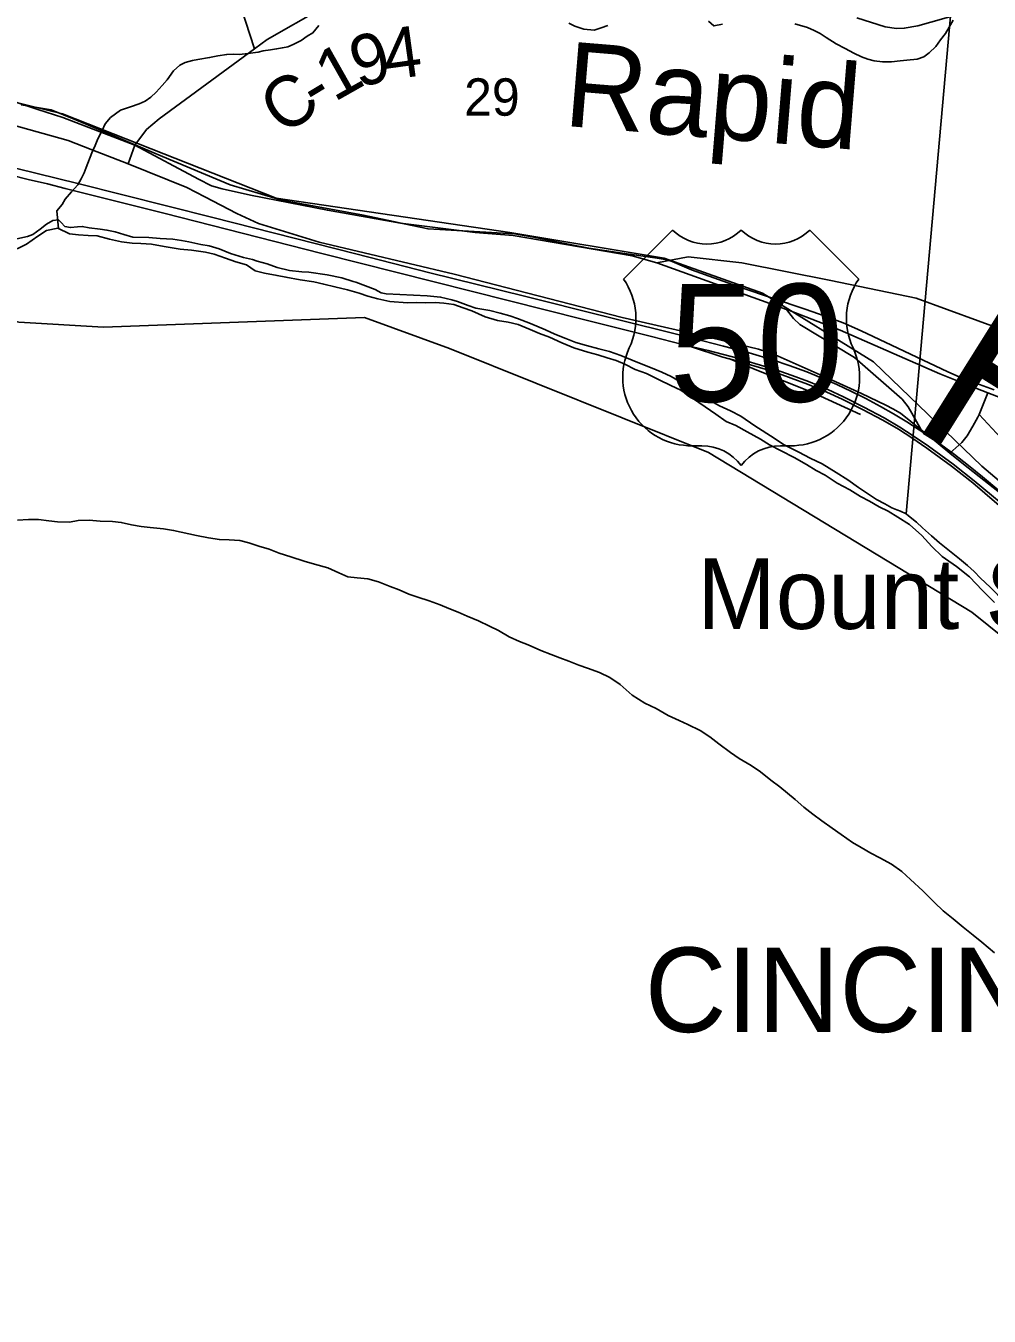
# Model space of a CAD drawing. Extents: x 0 to 34, y 0 to 22.
# Drawn here: x 4.65 to 5.729, y 14.739 to 16.185 of the extents above; entities that cross this region are included whole.
import ezdxf

# ---------------------------------------------------------------- set-up
doc = ezdxf.new("R2010")
doc.units = 0
for name, color, linetype in [('GM_X_City_Street', 7, 'Continuous'), ('GM_X_Corporation', 7, 'Continuous'), ('GM_X_Corporation_Text', 7, 'Continuous'), ('GM_X_County_Road', 7, 'Continuous'), ('GM_X_County_Road_Text', 7, 'Continuous'), ('GM_X_County_Text', 7, 'Continuous'), ('GM_X_Major_River', 7, 'Continuous'), ('GM_X_Minor_River', 7, 'Continuous'), ('GM_X_Minor_River_Text', 7, 'Continuous'), ('GM_X_Rail_Line', 7, 'Continuous'), ('GM_X_Section_Text', 7, 'Continuous'), ('GM_X_Unincorporated_Text', 7, 'Continuous'), ('GM_X_US_Location', 7, 'Continuous'), ('GM_X_US_Route', 7, 'Continuous'), ('GM_X_US_Shield', 7, 'Continuous')]:
    doc.layers.add(name, color=color, linetype=linetype)

msp = doc.modelspace()

# ---------------------------------------------------------------- linework, layer by layer
at = {"layer": 'GM_X_City_Street'}
for points in [[(5.6526, 15.7325), (5.6421, 15.751), (5.6381, 15.7581), (5.6313, 15.7667), (5.5781, 15.8133), (5.5166, 15.8504), (5.5098, 15.8571), (5.5019, 15.8673)], [(5.6849, 15.7062), (5.6984, 15.7183), (5.7041, 15.7255), (5.7107, 15.7365), (5.7163, 15.7467), (5.7175, 15.7496), (5.7275, 15.774)], [(5.7175, 15.7496), (5.7421, 15.7235), (5.752, 15.7145), (5.7596, 15.7096), (5.784, 15.6944)]]:
    msp.add_lwpolyline(points, dxfattribs=at)
at = {"layer": 'GM_X_Corporation'}
for points in [[(3.3535, 16.9293), (3.4766, 16.7367), (3.5579, 16.6419), (3.619, 16.5459), (3.7774, 16.2543), (3.8686, 16.1561), (3.9643, 16.0792), (4.2564, 15.9374), (4.3533, 15.9108), (4.4487, 15.8964), (4.6416, 15.8532), (4.7366, 15.8475), (5.0291, 15.8581), (5.1241, 15.8236), (5.4143, 15.7071), (5.7095, 15.5281), (5.8045, 15.4515), (6.1414, 15.0678), (6.2843, 14.8736), (6.3804, 14.7819), (6.459, 14.6859)], [(3.3535, 16.9293), (3.4766, 16.7367), (3.5579, 16.6419), (3.619, 16.5459), (3.7774, 16.2543), (3.8686, 16.1561), (3.9643, 16.0792), (4.2564, 15.9374), (4.3533, 15.9108), (4.4487, 15.8964), (4.6416, 15.8532), (4.7366, 15.8475), (5.0291, 15.8581), (5.1241, 15.8236), (5.4143, 15.7071), (5.7095, 15.5281), (5.8045, 15.4515), (6.1354, 15.0636), (6.1959, 14.9814), (6.2842, 14.8736), (6.3804, 14.7819), (6.459, 14.6859)], [(3.3535, 16.9293), (3.4766, 16.7367), (3.5579, 16.6419), (3.619, 16.5459), (3.7774, 16.2543), (3.8686, 16.1561), (3.9643, 16.0792), (4.2564, 15.9374), (4.3533, 15.9108), (4.4487, 15.8964), (4.6416, 15.8532), (4.7366, 15.8475), (5.0291, 15.8581), (5.1241, 15.8236), (5.4143, 15.7071), (5.7095, 15.5281), (5.8045, 15.4515), (6.1414, 15.0678), (6.2843, 14.8736), (6.3804, 14.7819), (6.459, 14.6859)], [(5.7092, 16.4608), (5.6358, 15.6382), (5.6294, 15.6414), (5.6253, 15.6426), (5.6197, 15.645), (5.6118, 15.6494), (5.6025, 15.6545), (5.5991, 15.6565), (5.5823, 15.6679), (5.5704, 15.6762), (5.5573, 15.6844), (5.5417, 15.6943), (5.5282, 15.7007), (5.5155, 15.7074), (5.4983, 15.7158), (5.4878, 15.7229), (5.4662, 15.737), (5.4505, 15.7476), (5.4389, 15.7536), (5.4266, 15.7592), (5.4049, 15.7711), (5.3814, 15.7868), (5.3724, 15.7923), (5.3623, 15.7971), (5.3496, 15.8024), (5.3353, 15.808), (5.3162, 15.8157), (5.3034, 15.8202), (5.2914, 15.8231), (5.2778, 15.8268), (5.2658, 15.8302), (5.2545, 15.8346), (5.2421, 15.8394), (5.2317, 15.8446), (5.2151, 15.8515), (5.2005, 15.8571), (5.1919, 15.86), (5.181, 15.8633), (5.1693, 15.8662), (5.1538, 15.8689), (5.1452, 15.8717), (5.1332, 15.8762), (5.1268, 15.8782), (5.1143, 15.8812), (5.0992, 15.8827), (5.0534, 15.8846), (5.0478, 15.8858), (5.0411, 15.8898), (5.0302, 15.8938), (5.0193, 15.8979), (5.0163, 15.8987), (5.0035, 15.9028), (4.9873, 15.9059), (4.9665, 15.909), (4.9589, 15.9096), (4.945, 15.9111), (4.931, 15.9144), (4.9201, 15.9185), (4.9089, 15.9214), (4.9036, 15.9231), (4.8934, 15.9256), (4.8788, 15.9301), (4.866, 15.9353), (4.8551, 15.9386), (4.8457, 15.94), (4.8321, 15.943), (4.8238, 15.9447), (4.8144, 15.9461), (4.8, 15.9468), (4.7875, 15.9478), (4.7693, 15.9483), (4.7592, 15.9512), (4.7498, 15.9541), (4.7404, 15.9562), (4.7328, 15.9571), (4.7207, 15.9589), (4.7128, 15.9603), (4.7075, 15.96), (4.6995, 15.9591), (4.6931, 15.9604), (4.689, 15.9646), (4.6861, 15.9677), (4.68, 15.9671), (4.6727, 15.9628), (4.6657, 15.9572), (4.6573, 15.9514), (4.6515, 15.9489), (4.6363, 15.9455)], [(5.7345, 15.7771), (5.7058, 15.7877), (5.6952, 15.7917), (5.6826, 15.7974), (5.5917, 15.8403), (5.5814, 15.8451), (5.5652, 15.8521), (5.5512, 15.8576), (5.5378, 15.8624), (5.5228, 15.8677), (5.4506, 15.892), (5.3953, 15.9117), (5.3876, 15.9151), (5.3736, 15.9209), (5.3682, 15.9227), (5.3638, 15.9238), (5.3569, 15.9248), (5.313, 15.9312), (5.2803, 15.9359), (5.2746, 15.9369), (5.2633, 15.9392), (5.2183, 15.9483), (5.1971, 15.9521), (5.1003, 15.9575), (5.0736, 15.9632), (5.0616, 15.9658), (5.028, 15.9729), (4.9363, 15.9896), (4.9313, 15.9911), (4.8785, 16.0068), (4.8026, 16.0386), (4.7287, 16.07), (4.7037, 16.0805), (4.6781, 16.0908), (4.6442, 16.0967)]]:
    msp.add_lwpolyline(points, dxfattribs=at)
msp.add_lwpolyline([(6.6267, 16.412), (6.5194, 15.3963), (5.7481, 15.5362), (5.7385, 15.5474), (5.73, 15.556), (5.7193, 15.5661), (5.7119, 15.5735), (5.7045, 15.5805), (5.6956, 15.5879), (5.6844, 15.5969), (5.6733, 15.6058), (5.6644, 15.6136), (5.6543, 15.6226), (5.6473, 15.6288), (5.6384, 15.6362), (5.6358, 15.6382), (5.7092, 16.4608)], close=True, dxfattribs=at)
at = {"layer": 'GM_X_County_Road'}
msp.add_line((4.7643, 16.0305), (4.7718, 16.0513), dxfattribs=at)
for points in [[(4.9057, 16.1593), (4.8909, 16.2054), (4.8786, 16.2563), (4.8733, 16.3037), (4.8803, 16.3426)], [(4.9057, 16.1593), (4.9201, 16.1698), (4.9815, 16.2049)], [(5.5805, 16.1941), (5.6125, 16.184), (5.625, 16.1822), (5.6337, 16.1824), (5.649, 16.1851), (5.6952, 16.1981)], [(4.7718, 16.0513), (4.7847, 16.0689), (4.799, 16.0807), (4.9057, 16.1593)], [(4.5521, 16.1152), (4.5559, 16.1144), (4.6024, 16.1062), (4.6382, 16.0994), (4.6632, 16.0913), (4.691, 16.0823), (4.7718, 16.0513)], [(4.7718, 16.0513), (4.8431, 16.0134), (4.8577, 16.0058), (4.8694, 16.0025), (4.9011, 15.9954), (4.9875, 15.9784), (5.0695, 15.9641), (5.1531, 15.9535), (5.1955, 15.9503), (5.3289, 15.9273), (5.3564, 15.9195), (5.5019, 15.8673), (5.5051, 15.8662), (5.5618, 15.8441), (5.6734, 15.795), (5.7072, 15.7818), (5.7275, 15.774), (5.7731, 15.7564)], [(5.3564, 15.9195), (5.3917, 15.9264), (5.4516, 15.9197), (5.5515, 15.8997), (5.647, 15.8798), (5.7513, 15.842), (5.8512, 15.7909), (5.9622, 15.7554), (6.0398, 15.7354), (6.1397, 15.7199), (6.2016, 15.7149)]]:
    msp.add_lwpolyline(points, dxfattribs=at)
at = {"layer": 'GM_X_Major_River'}
for points in [[(4.7686, 15.9416), (4.7568, 15.9429), (4.7432, 15.9461), (4.7296, 15.9498), (4.7194, 15.9503), (4.7084, 15.9509), (4.6986, 15.9522), (4.6854, 15.9584), (4.6728, 15.9556), (4.6632, 15.9493), (4.6502, 15.9404), (4.6399, 15.9352)], [(5.7349, 15.539), (5.7214, 15.5525), (5.7069, 15.5675), (5.6923, 15.5792), (5.6761, 15.5904), (5.6645, 15.6016), (5.6533, 15.6139), (5.6395, 15.6263), (5.6264, 15.6345), (5.6158, 15.6411), (5.6057, 15.6462), (5.5948, 15.6525), (5.5846, 15.6576), (5.5726, 15.665), (5.5587, 15.6728), (5.5452, 15.6817), (5.535, 15.6868), (5.5241, 15.6934), (5.5102, 15.7012), (5.4959, 15.7087), (5.4827, 15.7154), (5.4726, 15.722), (5.4579, 15.7302), (5.4451, 15.7372), (5.4342, 15.7419), (5.4226, 15.7501), (5.4106, 15.7583), (5.3835, 15.7769), (5.3722, 15.782), (5.3591, 15.7883), (5.3448, 15.7954), (5.3323, 15.8001), (5.3207, 15.806), (5.3109, 15.8099), (5.301, 15.8131), (5.2905, 15.8163), (5.2791, 15.8196), (5.2637, 15.8244), (5.2501, 15.8299), (5.2362, 15.8362), (5.2252, 15.8402), (5.2147, 15.8449), (5.2011, 15.8504), (5.1898, 15.8532), (5.178, 15.855), (5.1641, 15.859), (5.1494, 15.8657), (5.1396, 15.8692), (5.129, 15.8728), (5.118, 15.8745), (5.1082, 15.875), (5.0975, 15.8748), (5.0877, 15.875), (5.0771, 15.8748), (5.0574, 15.8762), (5.0438, 15.8791), (5.0328, 15.8823), (5.023, 15.8855), (5.0101, 15.8891), (4.9958, 15.8928), (4.9833, 15.8956), (4.9724, 15.8981), (4.9568, 15.9006), (4.941, 15.9035), (4.9311, 15.9052), (4.9171, 15.9081), (4.9065, 15.9105), (4.8968, 15.9171), (4.8847, 15.9207), (4.8734, 15.9247), (4.8606, 15.9291), (4.8507, 15.9315), (4.8352, 15.9337), (4.8223, 15.935), (4.8046, 15.9379), (4.7902, 15.9405), (4.7784, 15.941), (4.7686, 15.9416)], [(4.6404, 15.6312), (4.6526, 15.6318), (4.6636, 15.632), (4.6753, 15.6306), (4.6852, 15.6293), (4.6984, 15.6291), (4.7083, 15.6309), (4.7205, 15.6311), (4.733, 15.6301), (4.7466, 15.6295), (4.7565, 15.6286), (4.7678, 15.6261), (4.7788, 15.6241), (4.789, 15.6228), (4.8038, 15.6214), (4.8151, 15.6197), (4.8408, 15.614), (4.8541, 15.6115), (4.8665, 15.6094), (4.8775, 15.6092), (4.8893, 15.6083), (4.8995, 15.6058), (4.9108, 15.6022), (4.9221, 15.5986), (4.9334, 15.5943), (4.9463, 15.5899), (4.9614, 15.5851), (4.9731, 15.5819), (4.9878, 15.5778), (5.0002, 15.5723), (5.0104, 15.5676), (5.0206, 15.5667), (5.0328, 15.5654), (5.0448, 15.5621), (5.0577, 15.557), (5.0678, 15.553), (5.0788, 15.5483), (5.0886, 15.5447), (5.1014, 15.5407), (5.1139, 15.5364), (5.1236, 15.532), (5.1338, 15.5281), (5.144, 15.5237), (5.1568, 15.5182), (5.1692, 15.5123), (5.179, 15.5076), (5.1911, 15.5006), (5.2027, 15.4951), (5.2125, 15.4915), (5.2265, 15.4852), (5.2382, 15.4805), (5.248, 15.4769), (5.2578, 15.473), (5.2691, 15.4686), (5.2789, 15.4654), (5.2921, 15.4606), (5.3038, 15.4548), (5.3154, 15.447), (5.3289, 15.435), (5.3431, 15.426), (5.3556, 15.4202), (5.3691, 15.4123), (5.3815, 15.4068), (5.3913, 15.4021), (5.4049, 15.3955), (5.4158, 15.3885), (5.4259, 15.3807), (5.439, 15.371), (5.4488, 15.364), (5.4623, 15.3562), (5.4728, 15.3492), (5.4844, 15.3399), (5.4945, 15.3322)], [(5.4945, 15.3322), (5.5114, 15.3182), (5.5211, 15.3097), (5.5312, 15.3016), (5.5414, 15.2942), (5.553, 15.2861), (5.5631, 15.2791), (5.5759, 15.2698), (5.5856, 15.2643), (5.5962, 15.258), (5.6063, 15.2529), (5.6195, 15.2455), (5.6311, 15.2374), (5.6408, 15.2285), (5.6547, 15.2157), (5.6677, 15.2026), (5.6775, 15.1934), (5.6887, 15.1845), (5.6996, 15.1752), (5.7108, 15.1663), (5.7205, 15.1581), (5.7348, 15.1465)]]:
    msp.add_lwpolyline(points, dxfattribs=at)
at = {"layer": 'GM_X_Minor_River'}
for points in [[(4.6862, 15.958), (4.6843, 15.9777), (4.6901, 15.9848), (4.6937, 15.9909), (4.7007, 15.9991), (4.7077, 16.0069), (4.7117, 16.0137), (4.7149, 16.0205), (4.7172, 16.0262), (4.7237, 16.0428), (4.7272, 16.0511), (4.7304, 16.0586), (4.7352, 16.0677), (4.7384, 16.0752), (4.7446, 16.0823), (4.7558, 16.0905), (4.767, 16.0945), (4.7766, 16.0977), (4.7831, 16.1006), (4.7897, 16.1051), (4.7955, 16.1107), (4.8022, 16.1182), (4.808, 16.1245), (4.8151, 16.1347), (4.8221, 16.141), (4.8282, 16.1439), (4.8363, 16.1461), (4.8424, 16.1475), (4.8554, 16.1495), (4.8646, 16.1513), (4.8746, 16.153), (4.8822, 16.1532), (4.8891, 16.1531), (4.8983, 16.1541), (4.9098, 16.1554), (4.9155, 16.1572), (4.9236, 16.1582), (4.9305, 16.1592), (4.937, 16.1606), (4.9431, 16.1616), (4.9489, 16.1642), (4.9581, 16.1686), (4.9647, 16.1734), (4.9713, 16.1771), (4.9779, 16.1853)], [(5.2579, 16.1879), (5.2647, 16.1848), (5.2749, 16.1812), (5.2864, 16.1802), (5.2941, 16.1827), (5.3017, 16.1856)], [(5.4145, 16.1905), (5.4205, 16.185), (5.4301, 16.1871)], [(5.511, 16.1872), (5.5255, 16.1831), (5.5327, 16.18), (5.5395, 16.1764), (5.5463, 16.1721), (5.5576, 16.1651), (5.5674, 16.1596), (5.5773, 16.1545), (5.586, 16.1505), (5.5928, 16.1477), (5.6, 16.1457), (5.6092, 16.1448), (5.6195, 16.1446), (5.629, 16.1459), (5.6367, 16.1466), (5.6482, 16.1479), (5.6555, 16.1504), (5.6617, 16.1549), (5.6691, 16.162), (5.6745, 16.1695), (5.68, 16.1766), (5.684, 16.1837), (5.6887, 16.1913)]]:
    msp.add_lwpolyline(points, dxfattribs=at)
at = {"layer": 'GM_X_Rail_Line'}
for points in [[(4.6314, 16.1011), (4.6907, 16.0865), (4.93, 15.9918), (5.1919, 15.9535), (5.3649, 15.9246), (5.4749, 15.8856), (5.5993, 15.8085), (5.7206, 15.6918), (5.9364, 15.509), (6.0231, 15.4314), (6.3347, 15.0503), (6.5747, 14.7642), (6.7584, 14.6191)], [(4.5345, 16.0428), (4.6523, 16.013), (4.674, 16.0079), (4.6937, 16.0029), (4.8042, 15.9751), (4.9813, 15.9301), (5.2745, 15.8559), (5.3208, 15.8443), (5.3506, 15.8369), (5.3854, 15.8281), (5.4139, 15.8211), (5.447, 15.8126), (5.4662, 15.8069), (5.4878, 15.8003), (5.5082, 15.7931), (5.5264, 15.7864), (5.5482, 15.7774), (5.5656, 15.7692), (5.5883, 15.7579), (5.6111, 15.7458), (5.6287, 15.7355), (5.6438, 15.7257), (5.6607, 15.7142), (5.6885, 15.6939), (5.7122, 15.6751), (5.7619, 15.634)], [(4.6165, 16.0309), (4.7079, 16.0086), (4.8592, 15.9702), (5.0192, 15.9297), (5.1021, 15.9085), (5.2084, 15.8821), (5.2961, 15.8602), (5.3965, 15.8351), (5.4311, 15.8263), (5.4598, 15.8186), (5.4872, 15.8104), (5.5046, 15.8045), (5.5245, 15.7972), (5.545, 15.7888), (5.558, 15.7831), (5.5746, 15.7754), (5.5906, 15.7674), (5.6071, 15.7585), (5.6217, 15.7504), (5.6366, 15.7413), (5.6568, 15.7281), (5.6748, 15.7159), (5.6899, 15.7046), (5.7058, 15.6925), (5.7213, 15.6798), (5.7557, 15.6511)], [(5.3941, 15.8259), (5.4303, 15.8139), (5.4462, 15.8098), (5.4653, 15.8041), (5.4869, 15.7976), (5.5072, 15.7904), (5.5253, 15.7837), (5.547, 15.7747), (5.5643, 15.7666), (5.587, 15.7553), (5.6097, 15.7433), (5.6271, 15.733), (5.6421, 15.7233), (5.659, 15.7119), (5.6868, 15.6916), (5.7104, 15.6729), (5.7535, 15.6359)], [(5.437, 15.8122), (5.464, 15.801), (5.5308, 15.7741), (5.5848, 15.7497)]]:
    msp.add_lwpolyline(points, dxfattribs=at)
at = {"layer": 'GM_X_US_Route'}
for points in [[(4.6341, 16.0743), (4.6969, 16.0567), (4.7228, 16.0466), (4.7643, 16.0305), (4.8298, 16.004), (4.85, 15.9935), (4.8861, 15.9748), (4.9102, 15.9635), (4.9782, 15.9426), (5.1293, 15.9069), (5.3177, 15.8581), (5.4257, 15.8335), (5.4703, 15.8227), (5.4856, 15.8178), (5.5528, 15.7882), (5.5859, 15.7731), (5.6129, 15.7601), (5.6208, 15.7558), (5.6296, 15.751), (5.6526, 15.7325), (5.6607, 15.7259)], [(5.6607, 15.7259), (5.6849, 15.7062), (5.7001, 15.6939), (5.7736, 15.6359), (5.8456, 15.5757), (5.9188, 15.5196), (5.9615, 15.4831), (6.0011, 15.4472), (6.0397, 15.4044), (6.0794, 15.3568), (6.1454, 15.2774), (6.3518, 15.0271), (6.4684, 14.8825), (6.5421, 14.7942), (6.563, 14.7705), (6.5793, 14.7538), (6.6291, 14.714)]]:
    msp.add_lwpolyline(points, dxfattribs=at)
at = {"layer": 'GM_X_US_Shield'}
for p, q in [((5.3741, 15.9562), (5.3192, 15.9013)), ((5.5828, 15.9013), (5.5279, 15.9562)), ((5.3961, 15.7146), (5.4071, 15.7146)), ((5.495, 15.7146), (5.5059, 15.7146))]:
    msp.add_line(p, q, dxfattribs=at)
for centre, radius, start, end in [((5.4126, 15.9955), 0.0549, 225.573, 314.427), ((5.4895, 15.9955), 0.0549, 225.573, 314.427), ((5.2562, 15.8572), 0.0769, 334.5471, 35.0009), ((5.6458, 15.8572), 0.0769, 144.9991, 205.4529), ((5.3952, 15.7914), 0.0769, 154.8319, 270.6383), ((5.5068, 15.7914), 0.0769, 269.3617, 25.1681), ((5.4071, 15.6596), 0.0549, 36.8699, 90), ((5.495, 15.6596), 0.0549, 90, 143.1301)]:
    msp.add_arc(centre, radius, start, end, dxfattribs=at)

# ---------------------------------------------------------------- texts
at = {"layer": 'GM_X_Corporation_Text'}
msp.add_text('CINCINNATI', height=0.0947, rotation=0, dxfattribs=at).set_placement((5.3431, 15.0576))
at = {"layer": 'GM_X_County_Road_Text'}
for s, rotation, p in [('4', 7.8907, (5.0539, 16.124)), ('9', 15.5065, (5.0221, 16.1151)), ('1', 29.4812, (4.995, 16.0992)), ('C', 35.0785, (4.9381, 16.0611)), ('-', 31.1779, (4.9755, 16.0874))]:
    msp.add_text(s, height=0.0568, rotation=rotation, dxfattribs=at).set_placement(p)
at = {"layer": 'GM_X_County_Text'}
msp.add_text('H', height=0.1894, rotation=327.897, dxfattribs=at).set_placement((5.6367, 15.7389))
at = {"layer": 'GM_X_Minor_River_Text'}
msp.add_text('Rapid', height=0.0947, rotation=355.2876, dxfattribs=at).set_placement((5.2508, 16.0732))
at = {"layer": 'GM_X_Section_Text'}
msp.add_text('29', height=0.04186, rotation=0, dxfattribs=at).set_placement((5.1406, 16.0844))
at = {"layer": 'GM_X_Unincorporated_Text'}
msp.add_text('Mount Saint Joseph', height=0.078977, rotation=0, dxfattribs=at).set_placement((5.4018, 15.5093))
at = {"layer": 'GM_X_US_Location'}
for s, p in [('0', (5.4509, 15.8289)), ('/', (5.451, 15.8289))]:
    msp.add_text(s, height=0.000189, dxfattribs=at).set_placement(p)
msp.add_text('50', height=0.000189, rotation=0, dxfattribs=at).set_placement((5.4118, 15.7897))
at = {"layer": 'GM_X_US_Shield'}
msp.add_text('50', height=0.13184, dxfattribs=at).set_placement((5.3701, 15.764))

doc.saveas('drawing.dxf')
